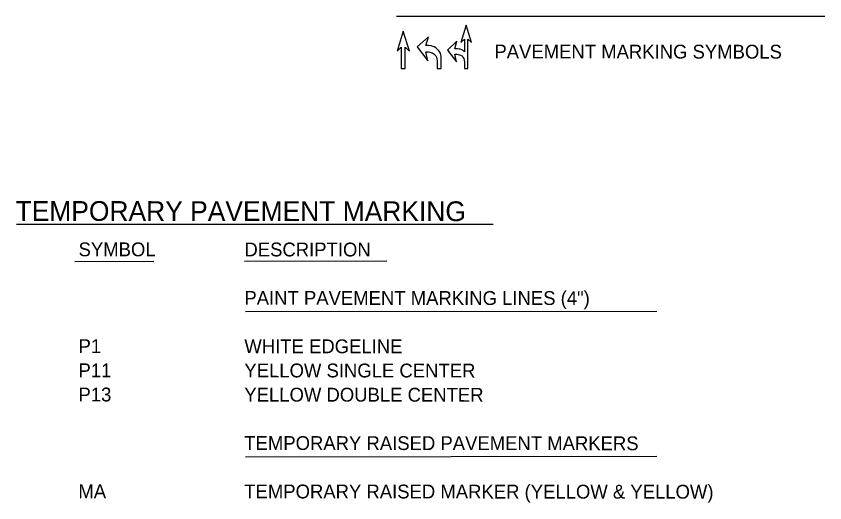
# Model space of a CAD drawing. Extents: x 0 to 1868, y 0 to 1100.
# Drawn here: x 1075.8 to 1485.4, y 299.9 to 546.2 of the extents above; entities that cross this region are included whole.
import ezdxf

# ---------------------------------------------------------------- set-up
doc = ezdxf.new("R2010")
doc.units = 0
doc.layers.add('P_RDY_ROW_Permanent_Easement_CELL', color=7, linetype='Continuous')

msp = doc.modelspace()

# ---------------------------------------------------------------- linework, layer by layer
at = {"layer": 'P_RDY_ROW_Permanent_Easement_CELL'}
for p, q in [((1268.45, 546.18), (1485.42, 546.18)), ((1075.97, 440.95), (1317.5, 440.95)), ((1105.47, 422.04), (1145.59, 422.11)), ((1191.55, 422.18), (1263.49, 422.29)), ((1191.95, 396.64), (1400.36, 396.88)), ((1191.9, 323.16), (1400.31, 323.4))]:
    msp.add_line(p, q, dxfattribs=at)
for points in [[(1304.66, 519.75), (1304.67, 534.61), (1306.52, 532.9), (1303.81, 541.62), (1301.09, 532.9), (1302.95, 534.62), (1302.95, 528.15), (1302.16, 528.77), (1301.56, 529.13), (1300.79, 529.41), (1300.16, 529.54), (1299.36, 529.65), (1297.95, 529.62), (1299.09, 533.47), (1294.23, 529.05), (1298.8, 523.04), (1297.94, 526.9), (1299.06, 526.88), (1299.72, 526.85), (1300.38, 526.69), (1300.95, 526.38), (1301.53, 526.06), (1302.1, 525.45), (1302.54, 524.71), (1302.82, 523.91), (1302.96, 523.01), (1302.94, 519.75)], [(1268.72, 528.42), (1270.89, 530.42), (1270.88, 519.76), (1272.88, 519.75), (1272.89, 530.42), (1275.06, 528.42), (1271.9, 538.59)], [(1289.12, 519.75), (1291.12, 519.75), (1291.13, 524.92), (1291.08, 525.87), (1290.95, 526.6), (1290.7, 527.38), (1290.35, 528.05), (1290.01, 528.55), (1289.44, 529.21), (1288.94, 529.65), (1288.34, 530.13), (1287.55, 530.6), (1286.92, 530.85), (1286.07, 531.1), (1284.91, 531.26), (1283.3, 531.26), (1284.64, 535.76), (1278.97, 530.59), (1284.29, 523.59), (1283.3, 528.09), (1284.63, 528.09), (1285.38, 528.05), (1286.07, 527.86), (1286.61, 527.61), (1287.3, 527.2), (1287.77, 526.82), (1288.31, 526.16), (1288.68, 525.4), (1288.97, 524.65), (1289.13, 523.59)]]:
    msp.add_lwpolyline(points, close=True, dxfattribs=at)

# ---------------------------------------------------------------- texts
for s, height, p in [('PAVEMENT MARKING SYMBOLS', 7, (1318.04, 524.81)), ('TEMPORARY PAVEMENT MARKING ', 10, (1075.51, 442.6)), ('SYMBOL ', 7, (1107.43, 424.67)), ('DESCRIPTION', 7, (1191.43, 424.61)), ('PAINT PAVEMENT MARKING LINES (4")', 7, (1191.41, 400.11)), ('P1', 7, (1107.4, 375.68)), ('WHITE EDGELINE', 7, (1191.4, 375.62)), ('P11', 7, (1107.39, 363.43)), ('YELLOW SINGLE CENTER', 7, (1191.39, 363.38)), ('P13', 7, (1107.38, 351.19)), ('YELLOW DOUBLE CENTER', 7, (1191.38, 351.13)), ('TEMPORARY RAISED PAVEMENT MARKERS', 7, (1191.36, 326.64)), ('MA', 7, (1107.34, 302.2)), ('TEMPORARY RAISED MARKER (YELLOW & YELLOW)', 7, (1191.34, 302.14))]:
    msp.add_text(s, height=height, rotation=359.9598, dxfattribs=at).set_placement(p)

doc.saveas('drawing.dxf')
